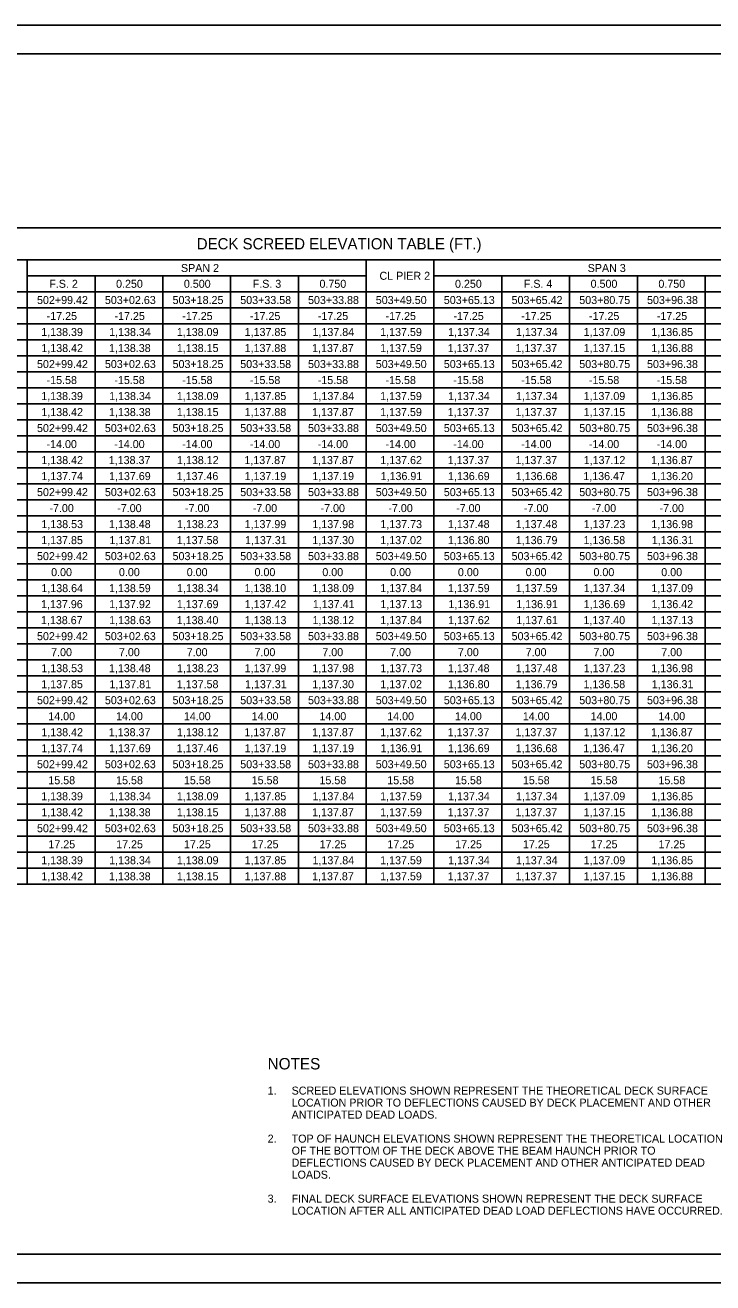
# Model space of a CAD drawing. Extents: x 0 to 34, y 0 to 22.
# Drawn here: x 11.77 to 23.8, y 0 to 22 of the extents above; entities that cross this region are included whole.
import ezdxf

# ---------------------------------------------------------------- set-up
doc = ezdxf.new("R2010")
doc.units = 0
for name, color, linetype in [('BR_P_Gen_Text', 7, 'Continuous'), ('Default', 7, 'Continuous'), ('SH_Border', 7, 'Continuous'), ('SH_Cut_Line', 7, 'Continuous')]:
    doc.layers.add(name, color=color, linetype=linetype)

msp = doc.modelspace()

# ---------------------------------------------------------------- linework, layer by layer
at = {"layer": 'Default'}
for p, q in [((1.531, 18.456), (31.969, 18.456)), ((1.531, 17.896), (31.969, 17.896)), ((11.809, 17.896), (11.809, 6.976)), ((17.738, 17.896), (17.738, 6.976)), ((18.924, 17.896), (18.924, 6.976)), ((11.809, 17.616), (17.738, 17.616)), ((12.995, 17.616), (12.995, 6.976)), ((14.181, 17.616), (14.181, 6.976)), ((15.366, 17.616), (15.366, 6.976)), ((16.552, 17.616), (16.552, 6.976)), ((18.924, 17.616), (24.854, 17.616)), ((20.11, 17.616), (20.11, 6.976)), ((21.296, 17.616), (21.296, 6.976)), ((22.482, 17.616), (22.482, 6.976)), ((23.668, 17.616), (23.668, 6.976)), ((1.531, 17.336), (31.969, 17.336)), ((2.585, 17.056), (31.969, 17.056)), ((2.585, 16.776), (31.969, 16.776)), ((2.585, 16.496), (31.969, 16.496)), ((1.531, 16.216), (31.969, 16.216)), ((2.585, 15.936), (31.969, 15.936)), ((2.585, 15.656), (31.969, 15.656)), ((2.585, 15.376), (31.969, 15.376)), ((1.531, 15.096), (31.969, 15.096)), ((2.585, 14.816), (31.969, 14.816)), ((2.585, 14.536), (31.969, 14.536)), ((2.585, 14.256), (31.969, 14.256)), ((1.531, 13.976), (31.969, 13.976)), ((2.585, 13.696), (31.969, 13.696)), ((2.585, 13.416), (31.969, 13.416)), ((2.585, 13.136), (31.969, 13.136)), ((1.531, 12.856), (31.969, 12.856)), ((2.585, 12.576), (31.969, 12.576)), ((2.585, 12.296), (31.969, 12.296)), ((2.585, 12.016), (31.969, 12.016)), ((2.585, 11.736), (31.969, 11.736)), ((1.531, 11.456), (31.969, 11.456)), ((2.585, 11.176), (31.969, 11.176)), ((2.585, 10.896), (31.969, 10.896)), ((2.585, 10.616), (31.969, 10.616)), ((1.531, 10.336), (31.969, 10.336)), ((2.585, 10.056), (31.969, 10.056)), ((2.585, 9.776), (31.969, 9.776)), ((2.585, 9.496), (31.969, 9.496)), ((1.531, 9.216), (31.969, 9.216)), ((2.585, 8.936), (31.969, 8.936)), ((2.585, 8.656), (31.969, 8.656)), ((2.585, 8.376), (31.969, 8.376)), ((1.531, 8.096), (31.969, 8.096)), ((2.585, 7.816), (31.969, 7.816)), ((2.585, 7.536), (31.969, 7.536)), ((2.585, 7.256), (31.969, 7.256)), ((1.531, 6.976), (31.969, 6.976))]:
    msp.add_line(p, q, dxfattribs=at)
at = {"layer": 'SH_Border'}
msp.add_lwpolyline([(1.5, 21.5), (33.5, 21.5), (33.5, 0.5), (1.5, 0.5)], close=True, dxfattribs=at)
at = {"layer": 'SH_Cut_Line'}
msp.add_lwpolyline([(0, 0), (34, 0), (34, 22), (0, 22)], close=True, dxfattribs=at)

# ---------------------------------------------------------------- texts
at = {"layer": 'BR_P_Gen_Text'}
for s, height, p in [('NOTES', 0.2, (16.014, 3.733)), ('1.', 0.14, (16.014, 3.293)), ('SCREED ELEVATIONS SHOWN REPRESENT THE THEORETICAL DECK SURFACE ', 0.14, (16.434, 3.293)), ('LOCATION PRIOR TO DEFLECTIONS CAUSED BY DECK PLACEMENT AND OTHER ', 0.14, (16.434, 3.083)), ('ANTICIPATED DEAD LOADS.', 0.14, (16.434, 2.873)), ('2.', 0.14, (16.014, 2.453)), ('TOP OF HAUNCH ELEVATIONS SHOWN REPRESENT THE THEORETICAL LOCATION ', 0.14, (16.434, 2.453)), ('OF THE BOTTOM OF THE DECK ABOVE THE BEAM HAUNCH PRIOR TO ', 0.14, (16.434, 2.243)), ('DEFLECTIONS CAUSED BY DECK PLACEMENT AND OTHER ANTICIPATED DEAD ', 0.14, (16.434, 2.033)), ('LOADS.', 0.14, (16.434, 1.823)), ('3.', 0.14, (16.014, 1.403)), ('FINAL DECK SURFACE ELEVATIONS SHOWN REPRESENT THE DECK SURFACE ', 0.14, (16.434, 1.403)), ('LOCATION AFTER ALL ANTICIPATED DEAD LOAD DEFLECTIONS HAVE OCCURRED.', 0.14, (16.434, 1.193))]:
    msp.add_text(s, height=height, dxfattribs=at).set_placement(p)
at = {"layer": 'Default'}
for s, height, p in [('DECK SCREED ELEVATION TABLE (FT.)', 0.196, (14.775, 18.078)), ('SPAN 2', 0.14, (14.498, 17.682)), ('SPAN 3', 0.14, (21.613, 17.682)), ('CL PIER 2', 0.14, (17.971, 17.546)), ('F.S. 2', 0.14, (12.195, 17.406)), ('0.250', 0.14, (13.363, 17.406)), ('0.500', 0.14, (14.549, 17.406)), ('F.S. 3', 0.14, (15.753, 17.406)), ('0.750', 0.14, (16.921, 17.406)), ('0.250', 0.14, (19.292, 17.406)), ('F.S. 4', 0.14, (20.496, 17.406)), ('0.500', 0.14, (21.664, 17.406)), ('0.750', 0.14, (22.85, 17.406)), ('502+99.42', 0.14, (11.98, 17.122)), ('503+02.63', 0.14, (13.167, 17.122)), ('503+18.25', 0.14, (14.351, 17.122)), ('503+33.58', 0.14, (15.535, 17.122)), ('503+33.88', 0.14, (16.721, 17.122)), ('503+49.50', 0.14, (17.906, 17.122)), ('503+65.13', 0.14, (19.096, 17.122)), ('503+65.42', 0.14, (20.282, 17.122)), ('503+80.75', 0.14, (21.466, 17.122)), ('503+96.38', 0.14, (22.651, 17.122)), ('-17.25', 0.14, (12.149, 16.842)), ('-17.25', 0.14, (13.335, 16.842)), ('-17.25', 0.14, (14.521, 16.842)), ('-17.25', 0.14, (15.706, 16.842)), ('-17.25', 0.14, (16.892, 16.842)), ('-17.25', 0.14, (18.078, 16.842)), ('-17.25', 0.14, (19.264, 16.842)), ('-17.25', 0.14, (20.45, 16.842)), ('-17.25', 0.14, (21.636, 16.842)), ('-17.25', 0.14, (22.822, 16.842)), ('1,138.39', 0.14, (12.054, 16.562)), ('1,138.34', 0.14, (13.242, 16.562)), ('1,138.09', 0.14, (14.426, 16.562)), ('1,137.85', 0.14, (15.612, 16.562)), ('1,137.84', 0.14, (16.799, 16.562)), ('1,137.59', 0.14, (17.983, 16.562)), ('1,137.34', 0.14, (19.171, 16.562)), ('1,137.34', 0.14, (20.357, 16.562)), ('1,137.09', 0.14, (21.541, 16.562)), ('1,136.85', 0.14, (22.727, 16.562)), ('1,138.42', 0.14, (12.056, 16.282)), ('1,138.38', 0.14, (13.239, 16.282)), ('1,138.15', 0.14, (14.426, 16.282)), ('1,137.88', 0.14, (15.611, 16.282)), ('1,137.87', 0.14, (16.792, 16.282)), ('1,137.59', 0.14, (17.983, 16.282)), ('1,137.37', 0.14, (19.164, 16.282)), ('1,137.37', 0.14, (20.35, 16.282)), ('1,137.15', 0.14, (21.541, 16.282)), ('1,136.88', 0.14, (22.726, 16.282)), ('502+99.42', 0.14, (11.98, 16.002)), ('503+02.63', 0.14, (13.167, 16.002)), ('503+18.25', 0.14, (14.351, 16.002)), ('503+33.58', 0.14, (15.535, 16.002)), ('503+33.88', 0.14, (16.721, 16.002)), ('503+49.50', 0.14, (17.906, 16.002)), ('503+65.13', 0.14, (19.096, 16.002)), ('503+65.42', 0.14, (20.282, 16.002)), ('503+80.75', 0.14, (21.466, 16.002)), ('503+96.38', 0.14, (22.651, 16.002)), ('-15.58', 0.14, (12.148, 15.722)), ('-15.58', 0.14, (13.333, 15.722)), ('-15.58', 0.14, (14.519, 15.722)), ('-15.58', 0.14, (15.705, 15.722)), ('-15.58', 0.14, (16.891, 15.722)), ('-15.58', 0.14, (18.077, 15.722)), ('-15.58', 0.14, (19.263, 15.722)), ('-15.58', 0.14, (20.449, 15.722)), ('-15.58', 0.14, (21.635, 15.722)), ('-15.58', 0.14, (22.82, 15.722)), ('1,138.39', 0.14, (12.054, 15.442)), ('1,138.34', 0.14, (13.242, 15.442)), ('1,138.09', 0.14, (14.426, 15.442)), ('1,137.85', 0.14, (15.612, 15.442)), ('1,137.84', 0.14, (16.799, 15.442)), ('1,137.59', 0.14, (17.983, 15.442)), ('1,137.34', 0.14, (19.171, 15.442)), ('1,137.34', 0.14, (20.357, 15.442)), ('1,137.09', 0.14, (21.541, 15.442)), ('1,136.85', 0.14, (22.727, 15.442)), ('1,138.42', 0.14, (12.056, 15.162)), ('1,138.38', 0.14, (13.239, 15.162)), ('1,138.15', 0.14, (14.426, 15.162)), ('1,137.88', 0.14, (15.611, 15.162)), ('1,137.87', 0.14, (16.792, 15.162)), ('1,137.59', 0.14, (17.983, 15.162)), ('1,137.37', 0.14, (19.164, 15.162)), ('1,137.37', 0.14, (20.35, 15.162)), ('1,137.15', 0.14, (21.541, 15.162)), ('1,136.88', 0.14, (22.726, 15.162)), ('502+99.42', 0.14, (11.98, 14.882)), ('503+02.63', 0.14, (13.167, 14.882)), ('503+18.25', 0.14, (14.351, 14.882)), ('503+33.58', 0.14, (15.535, 14.882)), ('503+33.88', 0.14, (16.721, 14.882)), ('503+49.50', 0.14, (17.906, 14.882)), ('503+65.13', 0.14, (19.096, 14.882)), ('503+65.42', 0.14, (20.282, 14.882)), ('503+80.75', 0.14, (21.466, 14.882)), ('503+96.38', 0.14, (22.651, 14.882)), ('-14.00', 0.14, (12.147, 14.602)), ('-14.00', 0.14, (13.332, 14.602)), ('-14.00', 0.14, (14.518, 14.602)), ('-14.00', 0.14, (15.704, 14.602)), ('-14.00', 0.14, (16.89, 14.602)), ('-14.00', 0.14, (18.076, 14.602)), ('-14.00', 0.14, (19.262, 14.602)), ('-14.00', 0.14, (20.448, 14.602)), ('-14.00', 0.14, (21.634, 14.602)), ('-14.00', 0.14, (22.82, 14.602)), ('1,138.42', 0.14, (12.056, 14.322)), ('1,138.37', 0.14, (13.235, 14.322)), ('1,138.12', 0.14, (14.428, 14.322)), ('1,137.87', 0.14, (15.607, 14.322)), ('1,137.87', 0.14, (16.792, 14.322)), ('1,137.62', 0.14, (17.985, 14.322)), ('1,137.37', 0.14, (19.164, 14.322)), ('1,137.37', 0.14, (20.35, 14.322)), ('1,137.12', 0.14, (21.543, 14.322)), ('1,136.87', 0.14, (22.722, 14.322)), ('1,137.74', 0.14, (12.056, 14.042)), ('1,137.69', 0.14, (13.24, 14.042)), ('1,137.46', 0.14, (14.423, 14.042)), ('1,137.19', 0.14, (15.611, 14.042)), ('1,137.19', 0.14, (16.797, 14.042)), ('1,136.91', 0.14, (17.991, 14.042)), ('1,136.69', 0.14, (19.169, 14.042)), ('1,136.68', 0.14, (20.354, 14.042)), ('1,136.47', 0.14, (21.536, 14.042)), ('1,136.20', 0.14, (22.725, 14.042)), ('502+99.42', 0.14, (11.98, 13.762)), ('503+02.63', 0.14, (13.167, 13.762)), ('503+18.25', 0.14, (14.351, 13.762)), ('503+33.58', 0.14, (15.535, 13.762)), ('503+33.88', 0.14, (16.721, 13.762)), ('503+49.50', 0.14, (17.906, 13.762)), ('503+65.13', 0.14, (19.096, 13.762)), ('503+65.42', 0.14, (20.282, 13.762)), ('503+80.75', 0.14, (21.466, 13.762)), ('503+96.38', 0.14, (22.651, 13.762)), ('-7.00', 0.14, (12.197, 13.482)), ('-7.00', 0.14, (13.383, 13.482)), ('-7.00', 0.14, (14.569, 13.482)), ('-7.00', 0.14, (15.754, 13.482)), ('-7.00', 0.14, (16.94, 13.482)), ('-7.00', 0.14, (18.126, 13.482)), ('-7.00', 0.14, (19.312, 13.482)), ('-7.00', 0.14, (20.498, 13.482)), ('-7.00', 0.14, (21.684, 13.482)), ('-7.00', 0.14, (22.87, 13.482)), ('1,138.53', 0.14, (12.056, 13.202)), ('1,138.48', 0.14, (13.239, 13.202)), ('1,138.23', 0.14, (14.428, 13.202)), ('1,137.99', 0.14, (15.611, 13.202)), ('1,137.98', 0.14, (16.797, 13.202)), ('1,137.73', 0.14, (17.986, 13.202)), ('1,137.48', 0.14, (19.168, 13.202)), ('1,137.48', 0.14, (20.354, 13.202)), ('1,137.23', 0.14, (21.543, 13.202)), ('1,136.98', 0.14, (22.726, 13.202)), ('1,137.85', 0.14, (12.054, 12.922)), ('1,137.81', 0.14, (13.247, 12.922)), ('1,137.58', 0.14, (14.425, 12.922)), ('1,137.31', 0.14, (15.619, 12.922)), ('1,137.30', 0.14, (16.796, 12.922)), ('1,137.02', 0.14, (17.985, 12.922)), ('1,136.80', 0.14, (19.167, 12.922)), ('1,136.79', 0.14, (20.355, 12.922)), ('1,136.58', 0.14, (21.54, 12.922)), ('1,136.31', 0.14, (22.734, 12.922)), ('502+99.42', 0.14, (11.98, 12.642)), ('503+02.63', 0.14, (13.167, 12.642)), ('503+18.25', 0.14, (14.351, 12.642)), ('503+33.58', 0.14, (15.535, 12.642)), ('503+33.88', 0.14, (16.721, 12.642)), ('503+49.50', 0.14, (17.906, 12.642)), ('503+65.13', 0.14, (19.096, 12.642)), ('503+65.42', 0.14, (20.282, 12.642)), ('503+80.75', 0.14, (21.466, 12.642)), ('503+96.38', 0.14, (22.651, 12.642)), ('0.00', 0.14, (12.227, 12.362)), ('0.00', 0.14, (13.413, 12.362)), ('0.00', 0.14, (14.599, 12.362)), ('0.00', 0.14, (15.785, 12.362)), ('0.00', 0.14, (16.971, 12.362)), ('0.00', 0.14, (18.157, 12.362)), ('0.00', 0.14, (19.343, 12.362)), ('0.00', 0.14, (20.528, 12.362)), ('0.00', 0.14, (21.714, 12.362)), ('0.00', 0.14, (22.9, 12.362)), ('1,138.64', 0.14, (12.056, 12.082)), ('1,138.59', 0.14, (13.24, 12.082)), ('1,138.34', 0.14, (14.428, 12.082)), ('1,138.10', 0.14, (15.61, 12.082)), ('1,138.09', 0.14, (16.797, 12.082)), ('1,137.84', 0.14, (17.985, 12.082)), ('1,137.59', 0.14, (19.169, 12.082)), ('1,137.59', 0.14, (20.355, 12.082)), ('1,137.34', 0.14, (21.543, 12.082)), ('1,137.09', 0.14, (22.727, 12.082)), ('1,137.96', 0.14, (12.051, 11.802)), ('1,137.92', 0.14, (13.242, 11.802)), ('1,137.69', 0.14, (14.426, 11.802)), ('1,137.42', 0.14, (15.613, 11.802)), ('1,137.41', 0.14, (16.805, 11.802)), ('1,137.13', 0.14, (17.986, 11.802)), ('1,136.91', 0.14, (19.177, 11.802)), ('1,136.91', 0.14, (20.363, 11.802)), ('1,136.69', 0.14, (21.541, 11.802)), ('1,136.42', 0.14, (22.729, 11.802)), ('1,138.67', 0.14, (12.049, 11.522)), ('1,138.63', 0.14, (13.242, 11.522)), ('1,138.40', 0.14, (14.424, 11.522)), ('1,138.13', 0.14, (15.614, 11.522)), ('1,138.12', 0.14, (16.799, 11.522)), ('1,137.84', 0.14, (17.985, 11.522)), ('1,137.62', 0.14, (19.171, 11.522)), ('1,137.61', 0.14, (20.363, 11.522)), ('1,137.40', 0.14, (21.539, 11.522)), ('1,137.13', 0.14, (22.729, 11.522)), ('502+99.42', 0.14, (11.98, 11.242)), ('503+02.63', 0.14, (13.167, 11.242)), ('503+18.25', 0.14, (14.351, 11.242)), ('503+33.58', 0.14, (15.535, 11.242)), ('503+33.88', 0.14, (16.721, 11.242)), ('503+49.50', 0.14, (17.906, 11.242)), ('503+65.13', 0.14, (19.096, 11.242)), ('503+65.42', 0.14, (20.282, 11.242)), ('503+80.75', 0.14, (21.466, 11.242)), ('503+96.38', 0.14, (22.651, 11.242)), ('7.00', 0.14, (12.227, 10.962)), ('7.00', 0.14, (13.413, 10.962)), ('7.00', 0.14, (14.599, 10.962)), ('7.00', 0.14, (15.785, 10.962)), ('7.00', 0.14, (16.971, 10.962)), ('7.00', 0.14, (18.157, 10.962)), ('7.00', 0.14, (19.343, 10.962)), ('7.00', 0.14, (20.528, 10.962)), ('7.00', 0.14, (21.714, 10.962)), ('7.00', 0.14, (22.9, 10.962)), ('1,138.53', 0.14, (12.056, 10.682)), ('1,138.48', 0.14, (13.239, 10.682)), ('1,138.23', 0.14, (14.428, 10.682)), ('1,137.99', 0.14, (15.611, 10.682)), ('1,137.98', 0.14, (16.797, 10.682)), ('1,137.73', 0.14, (17.986, 10.682)), ('1,137.48', 0.14, (19.168, 10.682)), ('1,137.48', 0.14, (20.354, 10.682)), ('1,137.23', 0.14, (21.543, 10.682)), ('1,136.98', 0.14, (22.726, 10.682)), ('1,137.85', 0.14, (12.054, 10.402)), ('1,137.81', 0.14, (13.247, 10.402)), ('1,137.58', 0.14, (14.425, 10.402)), ('1,137.31', 0.14, (15.619, 10.402)), ('1,137.30', 0.14, (16.796, 10.402)), ('1,137.02', 0.14, (17.985, 10.402)), ('1,136.80', 0.14, (19.167, 10.402)), ('1,136.79', 0.14, (20.355, 10.402)), ('1,136.58', 0.14, (21.54, 10.402)), ('1,136.31', 0.14, (22.734, 10.402)), ('502+99.42', 0.14, (11.98, 10.122)), ('503+02.63', 0.14, (13.167, 10.122)), ('503+18.25', 0.14, (14.351, 10.122)), ('503+33.58', 0.14, (15.535, 10.122)), ('503+33.88', 0.14, (16.721, 10.122)), ('503+49.50', 0.14, (17.906, 10.122)), ('503+65.13', 0.14, (19.096, 10.122)), ('503+65.42', 0.14, (20.282, 10.122)), ('503+80.75', 0.14, (21.466, 10.122)), ('503+96.38', 0.14, (22.651, 10.122)), ('14.00', 0.14, (12.177, 9.842)), ('14.00', 0.14, (13.363, 9.842)), ('14.00', 0.14, (14.549, 9.842)), ('14.00', 0.14, (15.735, 9.842)), ('14.00', 0.14, (16.921, 9.842)), ('14.00', 0.14, (18.106, 9.842)), ('14.00', 0.14, (19.292, 9.842)), ('14.00', 0.14, (20.478, 9.842)), ('14.00', 0.14, (21.664, 9.842)), ('14.00', 0.14, (22.85, 9.842)), ('1,138.42', 0.14, (12.056, 9.562)), ('1,138.37', 0.14, (13.235, 9.562)), ('1,138.12', 0.14, (14.428, 9.562)), ('1,137.87', 0.14, (15.607, 9.562)), ('1,137.87', 0.14, (16.792, 9.562)), ('1,137.62', 0.14, (17.985, 9.562)), ('1,137.37', 0.14, (19.164, 9.562)), ('1,137.37', 0.14, (20.35, 9.562)), ('1,137.12', 0.14, (21.543, 9.562)), ('1,136.87', 0.14, (22.722, 9.562)), ('1,137.74', 0.14, (12.056, 9.282)), ('1,137.69', 0.14, (13.24, 9.282)), ('1,137.46', 0.14, (14.423, 9.282)), ('1,137.19', 0.14, (15.611, 9.282)), ('1,137.19', 0.14, (16.797, 9.282)), ('1,136.91', 0.14, (17.991, 9.282)), ('1,136.69', 0.14, (19.169, 9.282)), ('1,136.68', 0.14, (20.354, 9.282)), ('1,136.47', 0.14, (21.536, 9.282)), ('1,136.20', 0.14, (22.725, 9.282)), ('502+99.42', 0.14, (11.98, 9.002)), ('503+02.63', 0.14, (13.167, 9.002)), ('503+18.25', 0.14, (14.351, 9.002)), ('503+33.58', 0.14, (15.535, 9.002)), ('503+33.88', 0.14, (16.721, 9.002)), ('503+49.50', 0.14, (17.906, 9.002)), ('503+65.13', 0.14, (19.096, 9.002)), ('503+65.42', 0.14, (20.282, 9.002)), ('503+80.75', 0.14, (21.466, 9.002)), ('503+96.38', 0.14, (22.651, 9.002)), ('15.58', 0.14, (12.178, 8.722)), ('15.58', 0.14, (13.364, 8.722)), ('15.58', 0.14, (14.55, 8.722)), ('15.58', 0.14, (15.736, 8.722)), ('15.58', 0.14, (16.921, 8.722)), ('15.58', 0.14, (18.107, 8.722)), ('15.58', 0.14, (19.293, 8.722)), ('15.58', 0.14, (20.479, 8.722)), ('15.58', 0.14, (21.665, 8.722)), ('15.58', 0.14, (22.851, 8.722)), ('1,138.39', 0.14, (12.054, 8.442)), ('1,138.34', 0.14, (13.242, 8.442)), ('1,138.09', 0.14, (14.426, 8.442)), ('1,137.85', 0.14, (15.612, 8.442)), ('1,137.84', 0.14, (16.799, 8.442)), ('1,137.59', 0.14, (17.983, 8.442)), ('1,137.34', 0.14, (19.171, 8.442)), ('1,137.34', 0.14, (20.357, 8.442)), ('1,137.09', 0.14, (21.541, 8.442)), ('1,136.85', 0.14, (22.727, 8.442)), ('1,138.42', 0.14, (12.056, 8.162)), ('1,138.38', 0.14, (13.239, 8.162)), ('1,138.15', 0.14, (14.426, 8.162)), ('1,137.88', 0.14, (15.611, 8.162)), ('1,137.87', 0.14, (16.792, 8.162)), ('1,137.59', 0.14, (17.983, 8.162)), ('1,137.37', 0.14, (19.164, 8.162)), ('1,137.37', 0.14, (20.35, 8.162)), ('1,137.15', 0.14, (21.541, 8.162)), ('1,136.88', 0.14, (22.726, 8.162)), ('502+99.42', 0.14, (11.98, 7.882)), ('503+02.63', 0.14, (13.167, 7.882)), ('503+18.25', 0.14, (14.351, 7.882)), ('503+33.58', 0.14, (15.535, 7.882)), ('503+33.88', 0.14, (16.721, 7.882)), ('503+49.50', 0.14, (17.906, 7.882)), ('503+65.13', 0.14, (19.096, 7.882)), ('503+65.42', 0.14, (20.282, 7.882)), ('503+80.75', 0.14, (21.466, 7.882)), ('503+96.38', 0.14, (22.651, 7.882)), ('17.25', 0.14, (12.179, 7.602)), ('17.25', 0.14, (13.365, 7.602)), ('17.25', 0.14, (14.551, 7.602)), ('17.25', 0.14, (15.737, 7.602)), ('17.25', 0.14, (16.923, 7.602)), ('17.25', 0.14, (18.109, 7.602)), ('17.25', 0.14, (19.295, 7.602)), ('17.25', 0.14, (20.48, 7.602)), ('17.25', 0.14, (21.666, 7.602)), ('17.25', 0.14, (22.852, 7.602)), ('1,138.39', 0.14, (12.054, 7.322)), ('1,138.34', 0.14, (13.242, 7.322)), ('1,138.09', 0.14, (14.426, 7.322)), ('1,137.85', 0.14, (15.612, 7.322)), ('1,137.84', 0.14, (16.799, 7.322)), ('1,137.59', 0.14, (17.983, 7.322)), ('1,137.34', 0.14, (19.171, 7.322)), ('1,137.34', 0.14, (20.357, 7.322)), ('1,137.09', 0.14, (21.541, 7.322)), ('1,136.85', 0.14, (22.727, 7.322)), ('1,138.42', 0.14, (12.056, 7.042)), ('1,138.38', 0.14, (13.239, 7.042)), ('1,138.15', 0.14, (14.426, 7.042)), ('1,137.88', 0.14, (15.611, 7.042)), ('1,137.87', 0.14, (16.792, 7.042)), ('1,137.59', 0.14, (17.983, 7.042)), ('1,137.37', 0.14, (19.164, 7.042)), ('1,137.37', 0.14, (20.35, 7.042)), ('1,137.15', 0.14, (21.541, 7.042)), ('1,136.88', 0.14, (22.726, 7.042))]:
    msp.add_text(s, height=height, dxfattribs=at).set_placement(p)

doc.saveas('drawing.dxf')
